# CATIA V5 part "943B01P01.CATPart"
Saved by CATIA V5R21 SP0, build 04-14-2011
Part number: 943B01P01
Bounding box of the stored display mesh (mm): x -33.4 to 33.4, y -127 to 127, z -8 to 72
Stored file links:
  C:\Users\ALI OZGUN\Desktop\alhan\943B01P01.CATPart
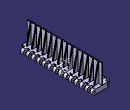
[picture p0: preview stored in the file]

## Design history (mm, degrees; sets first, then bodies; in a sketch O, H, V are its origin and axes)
Body1 (main body)
  Sketch1 on zx-plane, origin (0, 0, 0), H (-1, 0, 0), V (0, 0, 1)
    construction line L1 (25.4, 8) -> (25.4, -8)
    line L2 (25.4, -8) -> (-25.4, -8)
    construction line L3 (-25.4, -8) -> (-25.4, 8)
    line L4 (-25.4, 8) -> (25.4, 8)
    point P3 (-25.4, -8)
    arc A1 centre (25.4, 0) radius 8 from (25.4, 8) to (25.4, -8) cw
    arc A2 centre (-25.4, 0) radius 8 from (-25.4, 8) to (-25.4, -8) ccw
    point P7 (-25.4, -8)
    length L4 = 50.8
    length L3 = 16
    vertical: L1 V, L3 V
    horizontal: L2 H, L4 H
    equidistance: L1 L3 O, L2 L4 O
    tangency: A1 L2, A2 L4, A2 L2, L4 A1
    coincidence: P7 L2, P3 P7
  Pad1: profile Sketch1, direction (0, 1, 0), length 127, mirrored extent
  Sketch2 on zx-plane, origin (0, 0, 0), H (-1, 0, 0), V (0, 0, 1)
    circle A1 centre (25.4, 0) radius 3.15
    circle A2 centre (-25.4, 0) radius 3.15
    radius A1 = 3.15
    radius A2 = 3.15
  Pocket1: profile Sketch2, direction (0, -1, 0), length 204, mirrored extent
  Body2
    Pad2: profile Sketch6, direction (0, 1, 0), length 126, mirrored extent, thin wall 3
    Body3
      Pad3: profile Sketch5, direction (-1, 0, 0), length 3, opposite side length 1
      Fillet1: radius 1, on start face of Pad3
      RectPattern1: of the body so far, direction 1 instances 25, spacing 9.9, along edge [face of Pad2 | face of Pad2] reversed
    Remove1: tool Body3
    Body4
      Sketch3 on face of Pad5 from Sketch7.L3, origin (0, 109, 0), H (-1, 0, 0), V (0, 0, 1)
        line L1 (-1.5, 7) -> (-1.5, 71)
        line L2 (-1.5, 71) -> (-15.4, 7)
        line L3 (-15.4, 7) -> (-1.5, 7)
      Pad4: profile Sketch3, direction (0, 1, 0), length 6.6, opposite side length -2.6
      Sketch4 on face of Pad4 from Sketch3.L1, origin (1.5, 0, 0), H (0, -1, 0), V (0, 0, 1)
        arc A1 centre (-113.6, 69) radius 2 from (-111.6, 69) to (-115.6, 69) ccw
      Pocket2: profile Sketch4, direction (1, 0, 0), length 6.6
      Fillet2: radius 1, on edge [face of Pad4 from Sketch3.L2 | end face of Pad4]; edge [start face of Pad4 | face of Pad4 from Sketch3.L2]
      RectPattern2: of the body so far, direction 1 instances 14, spacing 17.6, along edge [face of Pad2 | face of Pad2] reversed
    Add1: tool Body4
    Sketch5 on face of Pad2, origin (-1.5, 0, 0), H (0, -1, 0), V (0, 0, 1)
      line L1 (-119, 81.3074) -> (-116, 81.3074)
      line L2 (-116, 81.3074) -> (-116, -9.2146)
      line L3 (-116, -9.2146) -> (-119, -9.2146)
      line L4 (-119, -9.2146) -> (-119, 81.3074)
      reference projected line E1 (-126, 72) -> (-126, 6.9718) from edge [end face of Pad2 | face of Pad2]
      reference projected line E2 (126, 72) -> (126, 6.9718) from edge [face of Pad2 | start face of Pad2]
      reference projected line E3 (-126, 72) -> (-126, 6.9718) from edge [end face of Pad2 | face of Pad2]
      distance E1 E2 = 252 (reference)
      distance L2 L4 = 3
      distance L4 E3 = 7
      horizontal: L1 H, L3 H
      vertical: L2 V, L4 V
  Add2: tool Body2
  Body5
    Solid1: solid without history
  Remove2: tool Body5
  Body6
    Solid2: solid without history
  Remove3: tool Body6
  RemoveFace1: RemoveFaces (face of Solid1; face of Solid1; face of Pocket1 from Sketch2.A2; face of Pad1 from Sketch1.A2; face of Solid2)
  Body7
    Solid3: solid without history
    Body8
      Solid4: solid without history
    Add3: tool Body8
  Remove4: tool Body7
  Body9
    Solid5: solid without history
  Remove5: tool Body9
  Sketch6 on zx-plane, origin (0, 0, 0), H (-1, 0, 0), V (0, 0, 1)
    line L1 (0, 72) -> (0, 6.9718)
    point P1 (0, 72)
    reference projected line E1 (-25.4, -8) -> (25.4, -8) from edge [face of Pad1 from Sketch1.L2 | end face of Pad1]
    distance P1 E1 = 80
    coincidence: P1 V
    vertical: L1 V
Body10
  Sketch7 on face of Pad1 from Sketch1.L4, origin (0, 0, 8), H (1, 0, 0), V (0, 1, 0)
    line L1 (16.4, 118.2) -> (45.1506, 118.2)
    line L2 (45.1506, 118.2) -> (45.1506, 109)
    line L3 (45.1506, 109) -> (16.4, 109)
    line L4 (16.4, 109) -> (16.4, 118.2)
    reference projected line E1 (-25.4, 127) -> (25.4, 127) from edge [face of Pad1 from Sketch1.L4 | end face of Pad1]
    reference projected line E2 through (25.4, 0) direction (0, 1) from axis of face of Pad1 from Sketch1.A2
    distance L1 E1 = 8.8
    distance E2 L4 = 9
    distance L3 L1 = 9.2
    horizontal: L1 H, L3 H
    vertical: L2 V, L4 V
  Pad5: profile Sketch7, direction (0, 0, -1), length 18, mirrored extent
  RectPattern3: of Pad5, direction 1 instances 15, spacing 18.1, along axis of face of Pad1 from Sketch1.A2 reversed
Body11
  Sketch8 on zx-plane, origin (0, 0, 0), H (-1, 0, 0), V (0, 0, 1)
    line L1 (44.4522, -25.1527) -> (-46.7446, -25.1527)
    line L2 (-46.7446, -25.1527) -> (-46.7446, 6.8555)
    line L3 (-46.7446, 6.8555) -> (44.4522, 6.8555)
    line L4 (44.4522, 6.8555) -> (44.4522, -25.1527)
    horizontal: L1 H, L3 H
    vertical: L2 V, L4 V
  Pad6: profile Sketch8, direction (0, 1, 0), length 150.6, mirrored extent
  Body12
    Solid6: linked copy from another document
    Body13
      Solid7: solid without history
    Add4: tool Body13
  Remove6: tool Body12
  Sketch9 on face of Solid7, origin (0, -91.4, 0), H (1, 0, 0), V (0, 0, 1)
    point P1 (30.7476, -31.891)
    line L1 (30.7476, -31.891) -> (18.3595, -7.0171)
    point P2 (18.3595, -7.0171)
    line L2 (18.3595, -7.0171) -> (15.2234, -0.9087)
    point P3 (15.2234, -0.9087)
    line L3 (15.2234, -0.9087) -> (17.2919, 8.1705)
    point P4 (17.2919, 8.1705)
    point P5 (-18.3595, -7.0171)
    point P6 (-30.7476, -31.891)
    line L4 (-30.7476, -31.891) -> (-18.3595, -7.0171)
    point P7 (-15.2234, -0.9087)
    line L5 (-18.3595, -7.0171) -> (-15.2234, -0.9087)
    point P8 (-17.2919, 8.1705)
    line L6 (-15.2234, -0.9087) -> (-17.2919, 8.1705)
    line L7 (30.7476, -31.891) -> (-30.7476, -31.891)
    point P9 (-30.7476, -31.891)
    symmetry: P2 P5 V, P1 P6 V, L1 L4 V, P3 P7 V, L2 L5 V, P4 P8 V, L3 L6 V
    coincidence: P9 L4, P6 P9
    horizontal: L7 H
  Pocket3: profile Sketch9, direction (0, 1, 0), length 273.6, opposite side length 72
